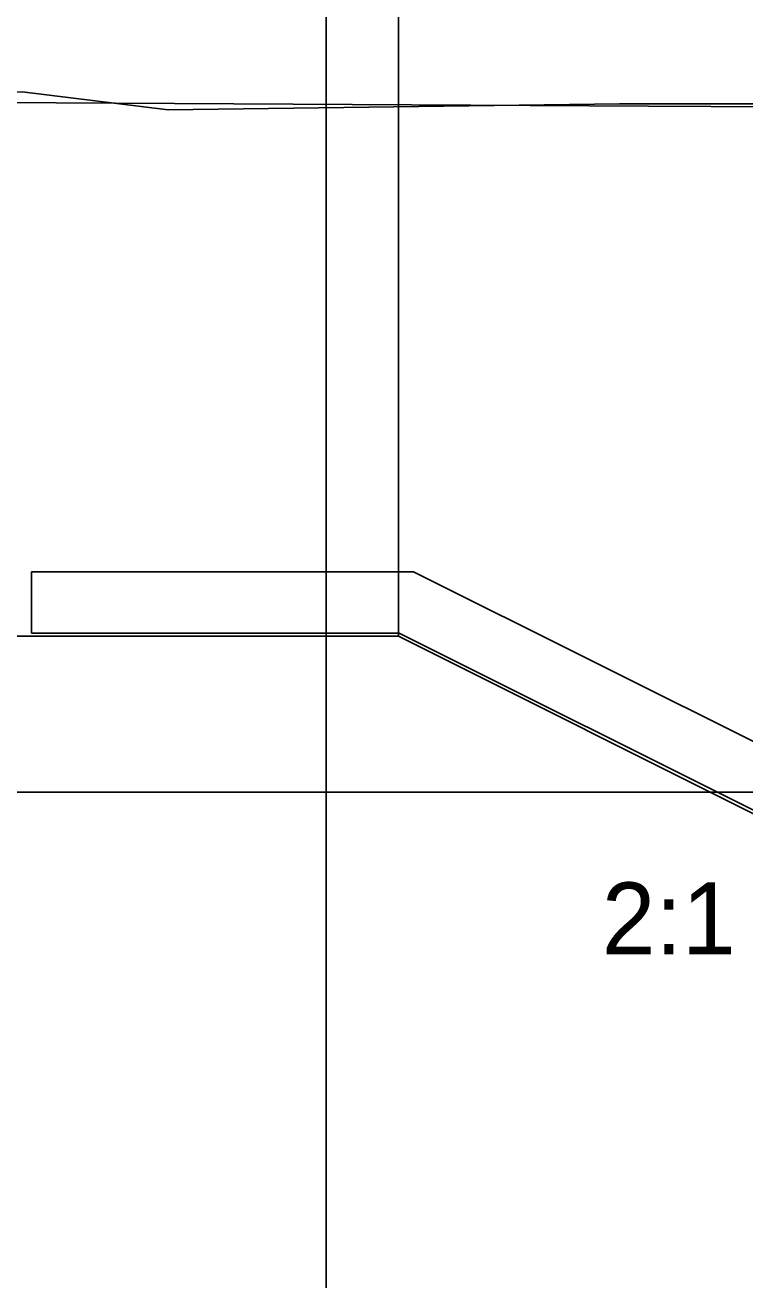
# Model space of a CAD drawing. Extents: x 1578769 to 1579225, y 724002 to 724828.
# Drawn here: x 1578859.27 to 1578863.96, y 724449.3 to 724457.47 of the extents above; entities that cross this region are included whole.
import ezdxf

# ---------------------------------------------------------------- set-up
doc = ezdxf.new("R2010")
doc.units = 0
for name, color, linetype in [('1', 7, 'Continuous'), ('Default', 7, 'Continuous'), ('Old_Level_41', 7, 'Continuous'), ('R_Exist Surface', 7, 'Continuous'), ('R_Fin Surface', 7, 'Continuous')]:
    doc.layers.add(name, color=color, linetype=linetype)

msp = doc.modelspace()

# ---------------------------------------------------------------- linework, layer by layer
at = {"layer": '1'}
msp.add_line((1578861.7014, 724453.4898), (1578861.7014, 724461.1985), dxfattribs=at)
at = {"layer": 'Default'}
msp.add_lwpolyline([(1578841.2303, 724457.0713), (1578842.2603, 724457.0594), (1578863.3303, 724456.9426), (1578874.2903, 724456.8851), (1578876.4003, 724454.7965), (1578883.1703, 724446.7822), (1578901.0203, 724441.7105), (1578903.4503, 724441.0286), (1578909.9203, 724441.3768), (1578926.3203, 724442.247), (1578964.0903, 724446.5535), (1578966.7003, 724446.865), (1578977.3903, 724447.8421), (1578995.6903, 724449.505), (1578999.6003, 724449.8412), (1579038.5003, 724453.3659)], dxfattribs=at)
at = {"layer": 'Old_Level_41'}
msp.add_line((1578861.2303, 724467.4737), (1578861.2303, 724437.4737), dxfattribs=at)
msp.add_lwpolyline([(1578821.2303, 724452.4737), (1578921.2303, 724452.4737)], dxfattribs=at)
at = {"layer": 'R_Exist Surface'}
msp.add_lwpolyline([(1578821.2303, 724457.0959), (1578841.2026, 724457.0731), (1578846.2342, 724457.0731), (1578848.2493, 724457.0932), (1578849.212, 724457.0151), (1578855.2225, 724457.0281), (1578858.2375, 724457.0216), (1578859.2523, 724457.0346), (1578860.202, 724456.9175), (1578863.1422, 724456.9565), (1578870.1545, 724456.9565), (1578871.1481, 724456.8987), (1578871.4213, 724456.8727), (1578874.2445, 724456.8987), (1578875.1161, 724456.0135), (1578876.1829, 724454.946), (1578880.2119, 724450.2709), (1578880.8595, 724449.5135), (1578883.2557, 724446.7468), (1578884.9705, 724446.2805), (1578895.0791, 724443.3873), (1578896.2567, 724443.0569)], dxfattribs=at)
at = {"layer": 'R_Fin Surface'}
for p, q in [((1578859.3116, 724453.5098), (1578859.3116, 724453.9098)), ((1578859.3116, 724453.9098), (1578861.8005, 724453.9098)), ((1578861.8005, 724453.9098), (1578867.8509, 724450.8846)), ((1578851.7014, 724453.4898), (1578861.7014, 724453.4898)), ((1578851.7014, 724453.4898), (1578861.7014, 724453.4898)), ((1578861.7061, 724453.5098), (1578859.3116, 724453.5098)), ((1578861.7014, 724453.4898), (1578867.7517, 724450.4646)), ((1578861.7014, 724453.4898), (1578867.7517, 724450.4646)), ((1578867.7564, 724450.4846), (1578861.7061, 724453.5098))]:
    msp.add_line(p, q, dxfattribs=at)

# ---------------------------------------------------------------- texts
at = {"layer": '1'}
msp.add_text('2:1', height=0.46875, dxfattribs=at).set_placement((1578863.0266, 724451.4176))

doc.saveas('drawing.dxf')
